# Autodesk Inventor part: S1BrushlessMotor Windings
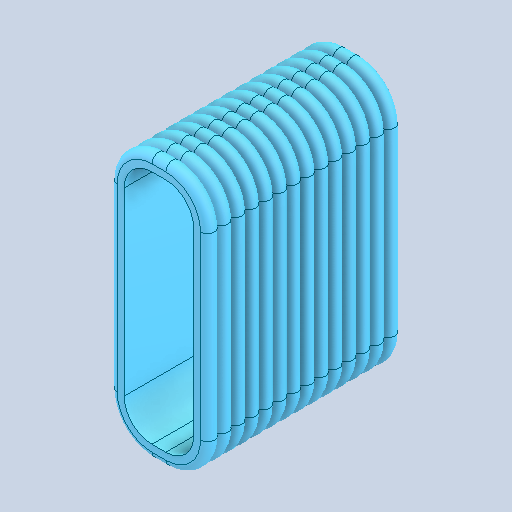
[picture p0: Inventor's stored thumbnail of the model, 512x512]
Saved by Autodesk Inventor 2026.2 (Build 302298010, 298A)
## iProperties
Created: 1601-01
Part Number: S1BrushlessMotor Windings
Material: Copper-Cobalt-Beryllium alloy, UNS C17500
Document SubType Name: Modeling
Designer: mel
Density: 8.75 g/cm^3
Appearance: brushed copper
Author: mel
Sending System: SOLIDWORKS 2023
Part Number: Motor Windings
Last Saved Date: 2025-04-02
last saved by: pierr
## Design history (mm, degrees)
feature "LPattern1"
node "Solide1"
